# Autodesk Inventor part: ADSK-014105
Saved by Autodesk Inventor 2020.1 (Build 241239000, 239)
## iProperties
_SkeletonDoc: Frame Skeleton File
_Version: 15.0.0
Part Number: ADSK-014105
Material: Allgemein
Description: Framegenerator-Skeleton-Referenz
Document SubType Name: Modellieren
Designer: lutzd
Density: 1 g/cm^3
Appearance: Vorgabe
DocNumber: ADSK-014105
Folder: .
Dimensions: 0x0x0 mm
Mass: 0 kg
Title: Gestellrahmenbauteil(e)
Author: lutzd
Revision Number: -
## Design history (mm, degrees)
sketch "Referenzrahmen"
node "Volumenkörper"
node "Flächenkörper"
